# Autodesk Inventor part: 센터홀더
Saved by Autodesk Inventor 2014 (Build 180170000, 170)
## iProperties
Created: 2026-09
Part Number: 센터홀더
Material: 일반
Document SubType Name: Modeling
Designer: dg
Density: 1 g/cm^3
Appearance: 기본값
Author: dg
Author: jhkim
Creation Date: 2026-08-27
Sending System: Autodesk Inventor 2027
Preprocessor: ST-DEVELOPER v20.1
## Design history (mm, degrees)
node "센터홀더1"
node "솔리드1"
node "기준1"
